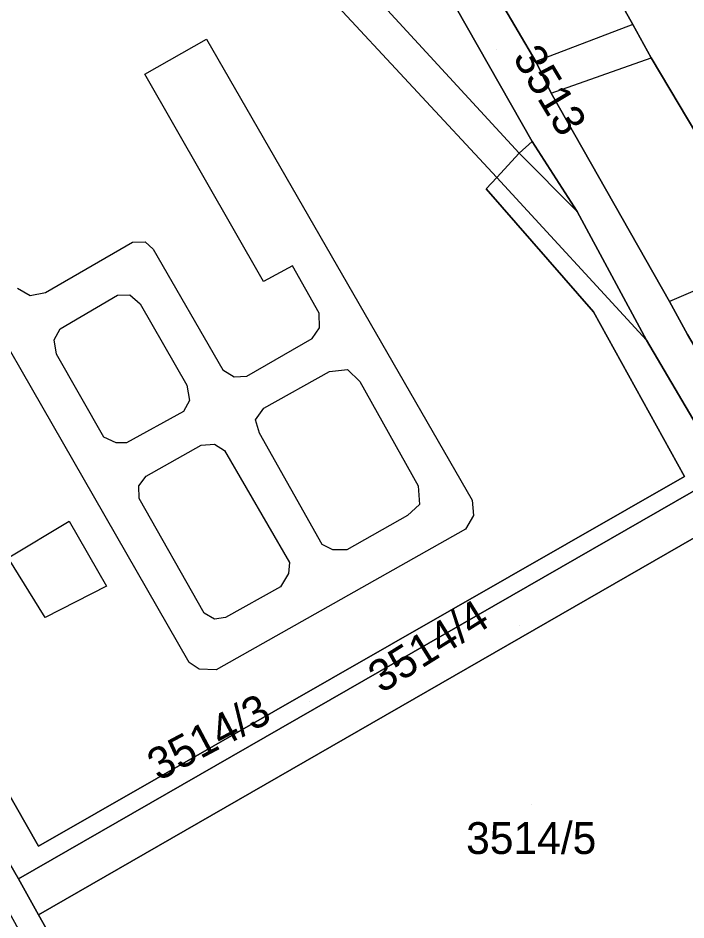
# Model space of a CAD drawing. Extents: x -262715 to -259381, y -1237238 to -1231182.
# Drawn here: x -261449.9 to -261408, y -1235802.5 to -1235745.8 of the extents above; entities that cross this region are included whole.
import ezdxf

# ---------------------------------------------------------------- set-up
doc = ezdxf.new("R2010")
doc.units = 0
for name, color, linetype in [('body_kn', 7, 'Continuous'), ('kladpar_druhypozemkov', 7, 'Continuous'), ('kladpar_hranice', 7, 'Continuous'), ('kladpar_parcelnecisla', 7, 'Continuous'), ('kladpar_plochy', 7, 'Continuous'), ('zappar_hrandruhpozemk', 7, 'Continuous')]:
    doc.layers.add(name, color=color, linetype=linetype)

msp = doc.modelspace()

# ---------------------------------------------------------------- linework, layer by layer
at = {"layer": 'body_kn'}
for p, q in [((-261411.3, -1235746.2), (-261411.3, -1235746.2)), ((-261411.3, -1235746.2), (-261411.3, -1235746.2)), ((-261438.08, -1235747.12), (-261438.08, -1235747.12)), ((-261417.4, -1235748.54), (-261417.4, -1235748.54)), ((-261410.15, -1235748.3), (-261410.15, -1235748.3)), ((-261441.97, -1235749.32), (-261441.97, -1235749.32)), ((-261416.42, -1235750.51), (-261416.42, -1235750.51)), ((-261416.42, -1235750.51), (-261416.42, -1235750.51)), ((-261417.63, -1235753.55), (-261417.63, -1235753.55)), ((-261418.44, -1235754.29), (-261418.44, -1235754.29)), ((-261418.44, -1235754.29), (-261418.44, -1235754.29)), ((-261419.84, -1235755.82), (-261419.84, -1235755.82)), ((-261419.84, -1235755.82), (-261419.84, -1235755.82)), ((-261420.52, -1235756.53), (-261420.52, -1235756.53)), ((-261414.79, -1235757.95), (-261414.79, -1235757.95)), ((-261442.73, -1235759.89), (-261442.73, -1235759.89)), ((-261441.95, -1235759.87), (-261441.95, -1235759.87)), ((-261441.44, -1235760.33), (-261441.44, -1235760.33)), ((-261432.68, -1235761.36), (-261432.68, -1235761.36)), ((-261434.5, -1235762.36), (-261434.5, -1235762.36)), ((-261449.17, -1235763.24), (-261449.17, -1235763.24)), ((-261448.21, -1235763.04), (-261448.21, -1235763.04)), ((-261443.69, -1235763.22), (-261443.69, -1235763.22)), ((-261442.9, -1235763.2), (-261442.9, -1235763.2)), ((-261442.25, -1235763.75), (-261442.25, -1235763.75)), ((-261408.99, -1235763.6), (-261408.99, -1235763.6)), ((-261431.01, -1235764.35), (-261431.01, -1235764.35)), ((-261413.76, -1235764.26), (-261413.76, -1235764.26)), ((-261447.29, -1235765.33), (-261447.29, -1235765.33)), ((-261430.99, -1235765.27), (-261430.99, -1235765.27)), ((-261447.67, -1235766.02), (-261447.67, -1235766.02)), ((-261431.45, -1235765.94), (-261431.45, -1235765.94)), ((-261410.44, -1235766.03), (-261410.44, -1235766.03)), ((-261410.44, -1235766.03), (-261410.44, -1235766.03)), ((-261447.52, -1235766.92), (-261447.52, -1235766.92)), ((-261437.06, -1235767.91), (-261437.06, -1235767.91)), ((-261436.34, -1235768.34), (-261436.34, -1235768.34)), ((-261435.55, -1235768.29), (-261435.55, -1235768.29)), ((-261430.35, -1235768.01), (-261430.35, -1235768.01)), ((-261429.22, -1235767.89), (-261429.22, -1235767.89)), ((-261439.32, -1235768.87), (-261439.32, -1235768.87)), ((-261439.32, -1235768.87), (-261439.32, -1235768.87)), ((-261428.45, -1235768.63), (-261428.45, -1235768.63)), ((-261439.15, -1235769.83), (-261439.15, -1235769.83)), ((-261439.54, -1235770.52), (-261439.54, -1235770.52)), ((-261434.48, -1235770.32), (-261434.48, -1235770.32)), ((-261435.01, -1235771.05), (-261435.01, -1235771.05)), ((-261444.54, -1235772.14), (-261444.54, -1235772.14)), ((-261434.76, -1235771.88), (-261434.76, -1235771.88)), ((-261434.76, -1235771.88), (-261434.76, -1235771.88)), ((-261443.76, -1235772.49), (-261443.76, -1235772.49)), ((-261443.12, -1235772.49), (-261443.12, -1235772.49)), ((-261438.42, -1235772.64), (-261438.42, -1235772.64)), ((-261437.59, -1235772.57), (-261437.59, -1235772.57)), ((-261436.96, -1235772.98), (-261436.96, -1235772.98)), ((-261441.87, -1235774.59), (-261441.87, -1235774.59)), ((-261441.87, -1235774.59), (-261441.87, -1235774.59)), ((-261408.06, -1235774.61), (-261408.06, -1235774.61)), ((-261442.34, -1235775.19), (-261442.34, -1235775.19)), ((-261424.78, -1235775.2), (-261424.78, -1235775.2)), ((-261442.32, -1235775.99), (-261442.32, -1235775.99)), ((-261424.71, -1235776.37), (-261424.71, -1235776.37)), ((-261421.4, -1235776.09), (-261421.4, -1235776.09)), ((-261446.71, -1235777.42), (-261446.71, -1235777.42)), ((-261446.71, -1235777.42), (-261446.71, -1235777.42)), ((-261425.46, -1235777.05), (-261425.46, -1235777.05)), ((-261421.3, -1235777.05), (-261421.3, -1235777.05)), ((-261421.82, -1235777.92), (-261421.82, -1235777.92)), ((-261430.82, -1235778.87), (-261430.82, -1235778.87)), ((-261430.14, -1235779.21), (-261430.14, -1235779.21)), ((-261429.27, -1235779.21), (-261429.27, -1235779.21)), ((-261432.88, -1235780.01), (-261432.88, -1235780.01)), ((-261432.94, -1235780.69), (-261432.94, -1235780.69)), ((-261444.37, -1235781.5), (-261444.37, -1235781.5)), ((-261433.44, -1235781.54), (-261433.44, -1235781.54)), ((-261438.23, -1235783.18), (-261438.23, -1235783.18)), ((-261448.22, -1235783.46), (-261448.22, -1235783.46)), ((-261437.58, -1235783.56), (-261437.58, -1235783.56)), ((-261436.89, -1235783.47), (-261436.89, -1235783.47)), ((-261439.18, -1235786.29), (-261439.18, -1235786.29)), ((-261438.55, -1235786.71), (-261438.55, -1235786.71)), ((-261437.48, -1235786.74), (-261437.48, -1235786.74)), ((-261448.64, -1235797.83), (-261448.64, -1235797.83)), ((-261449.9, -1235799.89), (-261449.9, -1235799.89)), ((-261448.64, -1235802.15), (-261448.64, -1235802.15))]:
    msp.add_line(p, q, dxfattribs=at)
at = {"layer": 'kladpar_druhypozemkov'}
for p, q in [((-261419.88, -1235747.76), (-261419.88, -1235747.76)), ((-261418.4, -1235783.99), (-261418.4, -1235783.99)), ((-261431.64, -1235788.74), (-261431.64, -1235788.74)), ((-261417.65, -1235795.2), (-261417.65, -1235795.2))]:
    msp.add_line(p, q, dxfattribs=at)
at = {"layer": 'kladpar_hranice'}
for points in [[(-261432.95, -1235706.96), (-261431.42, -1235709.75), (-261429.88, -1235712.54), (-261436.09, -1235715.42), (-261439.12, -1235716.82), (-261435.48, -1235723.07), (-261432.06, -1235728.17), (-261417.63, -1235753.55), (-261418.44, -1235754.29), (-261419.84, -1235755.82), (-261420.52, -1235756.53), (-261413.76, -1235764.26), (-261408.06, -1235774.61), (-261448.64, -1235797.83), (-261472.92, -1235755.22), (-261474.13, -1235753.11), (-261485.93, -1235732.67), (-261487.78, -1235733.38), (-261491.09, -1235724.4), (-261492.08, -1235722.2), (-261494.31, -1235717.51), (-261490.54, -1235706.42), (-261476.42, -1235698.22)], [(-261429.88, -1235712.54), (-261427.81, -1235716.31), (-261426.64, -1235718.44), (-261424.39, -1235722.53), (-261420.27, -1235730.03), (-261419.19, -1235732), (-261415.82, -1235738.13), (-261411.3, -1235746.2), (-261410.15, -1235748.3), (-261406.7, -1235754.1), (-261403.18, -1235761.14), (-261402.16, -1235762.98), (-261399.08, -1235768.58), (-261404.05, -1235772.18), (-261407.86, -1235765.69), (-261408.99, -1235763.6), (-261416.42, -1235750.51), (-261417.4, -1235748.54), (-261425.16, -1235735.31), (-261426.22, -1235733.27), (-261432.67, -1235721.52), (-261433.88, -1235719.33), (-261436.09, -1235715.42), (-261429.88, -1235712.54)], [(-261447.58, -1235807.24), (-261454.18, -1235795.37), (-261456.16, -1235792.23), (-261463.37, -1235779.52), (-261465.27, -1235776.58), (-261472.15, -1235764.41), (-261473.89, -1235761.17), (-261476.44, -1235757.01), (-261477.79, -1235754.49), (-261490.15, -1235734.26), (-261492.46, -1235725.42), (-261493.84, -1235725.81), (-261494.31, -1235717.51), (-261492.08, -1235722.2), (-261491.09, -1235724.4), (-261488.66, -1235733.71), (-261486.79, -1235735.32), (-261475.89, -1235754.88), (-261449.9, -1235799.89), (-261448.64, -1235802.15), (-261438.79, -1235819.6)], [(-261491.09, -1235724.4), (-261487.78, -1235733.38), (-261485.93, -1235732.67), (-261474.13, -1235753.11), (-261472.92, -1235755.22), (-261448.64, -1235797.83), (-261408.06, -1235774.61), (-261413.76, -1235764.26), (-261420.52, -1235756.53), (-261419.84, -1235755.82), (-261418.44, -1235754.29), (-261417.63, -1235753.55), (-261414.79, -1235757.95), (-261410.44, -1235766.03), (-261405.52, -1235774.39), (-261449.9, -1235799.89), (-261475.89, -1235754.88), (-261486.79, -1235735.32), (-261488.66, -1235733.71), (-261491.09, -1235724.4)], [(-261425.16, -1235735.31), (-261417.4, -1235748.54), (-261416.42, -1235750.51), (-261408.99, -1235763.6), (-261407.86, -1235765.69), (-261404.05, -1235772.18), (-261399.08, -1235768.58), (-261397.5, -1235767.72), (-261397.08, -1235768.52), (-261395.54, -1235771.47), (-261397.12, -1235772.37), (-261401.68, -1235775), (-261401.89, -1235775.34), (-261402.17, -1235776.14), (-261393.71, -1235791.5), (-261392.51, -1235792.14), (-261391.35, -1235791.92), (-261394.29, -1235794.7), (-261404.09, -1235776.52), (-261405.52, -1235774.39), (-261410.44, -1235766.03), (-261414.79, -1235757.95), (-261417.63, -1235753.55), (-261432.06, -1235728.17)], [(-261400.1, -1235741.16), (-261396.82, -1235747.15), (-261393.51, -1235753.17), (-261391.39, -1235752.01), (-261390.77, -1235753.15), (-261389.7, -1235755.09), (-261391.82, -1235756.26), (-261388.34, -1235762.58), (-261397.5, -1235767.72), (-261399.08, -1235768.58), (-261402.16, -1235762.98), (-261403.18, -1235761.14), (-261406.7, -1235754.1), (-261410.15, -1235748.3), (-261411.3, -1235746.2), (-261415.82, -1235738.13)], [(-261405.52, -1235774.39), (-261404.09, -1235776.52), (-261448.64, -1235802.15), (-261449.9, -1235799.89), (-261405.52, -1235774.39)], [(-261404.09, -1235776.52), (-261394.29, -1235794.7), (-261393.89, -1235795.44), (-261394.41, -1235795.96), (-261437.48, -1235820.77), (-261438.17, -1235820.11), (-261438.79, -1235819.6), (-261448.64, -1235802.15), (-261404.09, -1235776.52)]]:
    msp.add_lwpolyline(points, dxfattribs=at)
at = {"layer": 'kladpar_plochy'}
for points in [[(-261460.77, -1235676.58), (-261445.02, -1235705.07), (-261441.49, -1235711.7), (-261438.87, -1235710.25), (-261432.95, -1235706.96), (-261431.42, -1235709.75), (-261429.88, -1235712.54), (-261436.09, -1235715.42), (-261439.12, -1235716.82), (-261435.48, -1235723.07), (-261432.06, -1235728.17), (-261417.63, -1235753.55), (-261418.44, -1235754.29), (-261419.84, -1235755.82), (-261420.52, -1235756.53), (-261413.76, -1235764.26), (-261408.06, -1235774.61), (-261448.64, -1235797.83), (-261472.92, -1235755.22)], [(-261447.58, -1235807.24), (-261454.18, -1235795.37), (-261456.16, -1235792.23), (-261463.37, -1235779.52), (-261465.27, -1235776.58), (-261472.15, -1235764.41), (-261473.89, -1235761.17), (-261476.44, -1235757.01), (-261477.79, -1235754.49), (-261490.15, -1235734.26), (-261492.46, -1235725.42), (-261493.84, -1235725.81), (-261494.31, -1235717.51), (-261492.08, -1235722.2), (-261491.09, -1235724.4), (-261488.66, -1235733.71), (-261486.79, -1235735.32), (-261475.89, -1235754.88), (-261449.9, -1235799.89), (-261448.64, -1235802.15), (-261438.79, -1235819.6)], [(-261425.16, -1235735.31), (-261417.4, -1235748.54), (-261416.42, -1235750.51), (-261408.99, -1235763.6), (-261407.86, -1235765.69), (-261404.05, -1235772.18), (-261399.08, -1235768.58), (-261397.5, -1235767.72), (-261397.08, -1235768.52), (-261395.54, -1235771.47), (-261397.12, -1235772.37), (-261401.68, -1235775), (-261401.89, -1235775.34), (-261402.17, -1235776.14), (-261393.71, -1235791.5), (-261392.51, -1235792.14), (-261391.35, -1235791.92), (-261394.29, -1235794.7), (-261404.09, -1235776.52), (-261405.52, -1235774.39), (-261410.44, -1235766.03), (-261414.79, -1235757.95), (-261417.63, -1235753.55), (-261432.06, -1235728.17)], [(-261400.1, -1235741.16), (-261396.82, -1235747.15), (-261393.51, -1235753.17), (-261391.39, -1235752.01), (-261390.77, -1235753.15), (-261389.7, -1235755.09), (-261391.82, -1235756.26), (-261388.34, -1235762.58), (-261397.5, -1235767.72), (-261399.08, -1235768.58), (-261402.16, -1235762.98), (-261403.18, -1235761.14), (-261406.7, -1235754.1), (-261410.15, -1235748.3), (-261411.3, -1235746.2), (-261415.82, -1235738.13)]]:
    msp.add_lwpolyline(points, dxfattribs=at)
for points in [[(-261429.88, -1235712.54), (-261427.81, -1235716.31), (-261426.64, -1235718.44), (-261424.39, -1235722.53), (-261420.27, -1235730.03), (-261419.19, -1235732), (-261415.82, -1235738.13), (-261411.3, -1235746.2), (-261410.15, -1235748.3), (-261406.7, -1235754.1), (-261403.18, -1235761.14), (-261402.16, -1235762.98), (-261399.08, -1235768.58), (-261404.05, -1235772.18), (-261407.86, -1235765.69), (-261408.99, -1235763.6), (-261416.42, -1235750.51), (-261417.4, -1235748.54), (-261425.16, -1235735.31), (-261426.22, -1235733.27), (-261432.67, -1235721.52), (-261433.88, -1235719.33), (-261436.09, -1235715.42)], [(-261491.09, -1235724.4), (-261487.78, -1235733.38), (-261485.93, -1235732.67), (-261474.13, -1235753.11), (-261472.92, -1235755.22), (-261448.64, -1235797.83), (-261408.06, -1235774.61), (-261413.76, -1235764.26), (-261420.52, -1235756.53), (-261419.84, -1235755.82), (-261418.44, -1235754.29), (-261417.63, -1235753.55), (-261414.79, -1235757.95), (-261410.44, -1235766.03), (-261405.52, -1235774.39), (-261449.9, -1235799.89), (-261475.89, -1235754.88), (-261486.79, -1235735.32), (-261488.66, -1235733.71)], [(-261405.52, -1235774.39), (-261404.09, -1235776.52), (-261448.64, -1235802.15), (-261449.9, -1235799.89)], [(-261404.09, -1235776.52), (-261394.29, -1235794.7), (-261393.89, -1235795.44), (-261394.41, -1235795.96), (-261437.48, -1235820.77), (-261438.17, -1235820.11), (-261438.79, -1235819.6), (-261448.64, -1235802.15)]]:
    msp.add_lwpolyline(points, close=True, dxfattribs=at)
at = {"layer": 'zappar_hrandruhpozemk'}
for p, q in [((-261418.44, -1235754.29), (-261435.9, -1235735.29)), ((-261419.84, -1235755.82), (-261438.5, -1235735.75)), ((-261411.3, -1235746.2), (-261417.4, -1235748.54)), ((-261438.08, -1235747.12), (-261421.4, -1235776.09)), ((-261416.42, -1235750.51), (-261410.15, -1235748.3)), ((-261418.44, -1235754.29), (-261414.79, -1235757.95)), ((-261410.44, -1235766.03), (-261419.84, -1235755.82)), ((-261441.44, -1235760.33), (-261437.06, -1235767.91)), ((-261403.18, -1235761.14), (-261408.99, -1235763.6)), ((-261442.25, -1235763.75), (-261439.32, -1235768.87)), ((-261444.54, -1235772.14), (-261447.52, -1235766.92)), ((-261434.48, -1235770.32), (-261430.35, -1235768.01)), ((-261436.96, -1235772.98), (-261432.88, -1235780.01)), ((-261446.71, -1235777.42), (-261444.37, -1235781.5)), ((-261444.37, -1235781.5), (-261448.22, -1235783.46))]:
    msp.add_line(p, q, dxfattribs=at)
for points in [[(-261437.06, -1235767.91), (-261436.34, -1235768.34), (-261435.55, -1235768.29), (-261431.45, -1235765.94), (-261430.99, -1235765.27), (-261431.01, -1235764.35), (-261432.68, -1235761.36), (-261434.5, -1235762.36), (-261441.97, -1235749.32), (-261438.08, -1235747.12)], [(-261439.18, -1235786.29), (-261460.95, -1235748.38), (-261472.92, -1235755.22)], [(-261449.96, -1235762.78), (-261449.17, -1235763.24), (-261448.21, -1235763.04), (-261442.73, -1235759.89), (-261441.95, -1235759.87), (-261441.44, -1235760.33)], [(-261447.52, -1235766.92), (-261447.67, -1235766.02), (-261447.29, -1235765.33), (-261443.69, -1235763.22), (-261442.9, -1235763.2), (-261442.25, -1235763.75)], [(-261430.35, -1235768.01), (-261429.22, -1235767.89), (-261428.45, -1235768.63), (-261424.78, -1235775.2), (-261424.71, -1235776.37), (-261425.46, -1235777.05), (-261429.27, -1235779.21), (-261430.14, -1235779.21), (-261430.82, -1235778.87), (-261434.76, -1235771.88)], [(-261439.32, -1235768.87), (-261439.15, -1235769.83), (-261439.54, -1235770.52), (-261443.12, -1235772.49), (-261443.76, -1235772.49), (-261444.54, -1235772.14)], [(-261434.76, -1235771.88), (-261435.01, -1235771.05), (-261434.48, -1235770.32)], [(-261441.87, -1235774.59), (-261438.42, -1235772.64), (-261437.59, -1235772.57), (-261436.96, -1235772.98)], [(-261432.88, -1235780.01), (-261432.94, -1235780.69), (-261433.44, -1235781.54), (-261436.89, -1235783.47), (-261437.58, -1235783.56), (-261438.23, -1235783.18), (-261442.32, -1235775.99), (-261442.34, -1235775.19), (-261441.87, -1235774.59)], [(-261421.4, -1235776.09), (-261421.3, -1235777.05), (-261421.82, -1235777.92), (-261437.48, -1235786.74), (-261438.55, -1235786.71), (-261439.18, -1235786.29)], [(-261448.22, -1235783.46), (-261450.54, -1235779.71), (-261446.71, -1235777.42)]]:
    msp.add_lwpolyline(points, dxfattribs=at)

# ---------------------------------------------------------------- texts
at = {"layer": 'kladpar_parcelnecisla'}
for s, rotation, p in [('3513', 301, (-261418.882, -1235748.277)), ('3514/4', 32, (-261427.099, -1235788.265)), ('3514/3', 28, (-261441.101, -1235793.77))]:
    msp.add_text(s, height=2, rotation=rotation, dxfattribs=at).set_placement(p)
msp.add_text('3514/5', height=2, dxfattribs=at).set_placement((-261421.773, -1235798.32))

doc.saveas('drawing.dxf')
